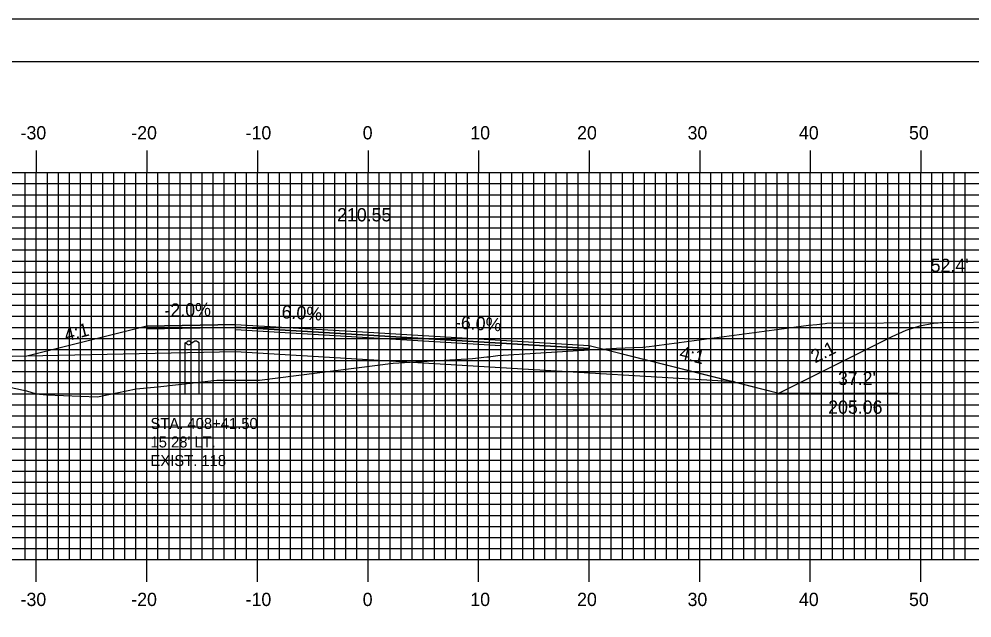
# Model space of a CAD drawing. Extents: x 852529 to 852872, y 364785 to 365005.
# Drawn here: x 852663.2 to 852749.3, y 364951 to 365005.1 of the extents above; entities that cross this region are included whole.
import ezdxf

# ---------------------------------------------------------------- set-up
doc = ezdxf.new("R2010")
doc.units = 0
for name, color, linetype in [('ANNOTATION', 7, 'Continuous'), ('BORDER', 7, 'Continuous'), ('D_Roadway_Centerline', 7, 'Continuous'), ('D_Roadway_Centerline_Text', 7, 'Continuous'), ('D_Roadway_Edge_Shoulder', 7, 'Continuous'), ('D_Roadway_Edge_TW', 7, 'Continuous'), ('D_Roadway_FinishedGrade', 7, 'Continuous'), ('D_Roadway_Pavement', 7, 'Continuous'), ('D_Roadway_SlopeLines', 7, 'Continuous'), ('D_Roadway_SubGrade', 7, 'Continuous'), ('D_Text_Monospaced', 7, 'Continuous'), ('D_Text_Standard', 7, 'Continuous'), ('H_V ANNOTATION', 7, 'Continuous'), ('MAJOR', 7, 'Continuous'), ('MINOR', 7, 'Continuous'), ('PDRAIN', 7, 'Continuous'), ('PLOT BOUNDARY', 7, 'Continuous'), ('S_Roadway_Centerline', 7, 'Continuous'), ('S_Utilities_Pole_Power', 7, 'Continuous')]:
    doc.layers.add(name, color=color, linetype=linetype)

msp = doc.modelspace()

# ---------------------------------------------------------------- linework, layer by layer
at = {"layer": 'ANNOTATION'}
msp.add_line((852663.861, 364974.628), (852637.933, 364974.11), dxfattribs=at)
at = {"layer": 'BORDER'}
msp.add_lwpolyline([(852545.131, 364791.233), (852865.131, 364791.233), (852865.131, 365001.233), (852545.131, 365001.233)], close=True, dxfattribs=at)
at = {"layer": 'D_Roadway_Centerline'}
msp.add_lwpolyline([(852674.731, 364977.346), (852682.731, 364977.506), (852694.731, 364976.786), (852706.731, 364976.066), (852714.731, 364975.586), (852727.889, 364972.296), (852731.889, 364971.296), (852742.137, 364976.42), (852743.387, 364976.968), (852744.637, 364977.363), (852745.887, 364977.603), (852747.137, 364977.69)], dxfattribs=at)
at = {"layer": 'D_Roadway_Edge_Shoulder'}
for points in [[(852682.731, 364977.506), (852674.731, 364977.346), (852674.731, 364977.096), (852682.731, 364977.256)], [(852706.731, 364976.066), (852714.731, 364975.586), (852714.731, 364975.336), (852706.731, 364975.816)]]:
    msp.add_lwpolyline(points, close=True, dxfattribs=at)
at = {"layer": 'D_Roadway_Edge_TW'}
msp.add_lwpolyline([(852682.731, 364977.256), (852682.731, 364977.506), (852694.731, 364976.786), (852706.731, 364976.066), (852706.731, 364975.816), (852694.731, 364976.536)], close=True, dxfattribs=at)
at = {"layer": 'D_Roadway_FinishedGrade'}
msp.add_line((852674.731, 364977.346), (852663.861, 364974.628), dxfattribs=at)
at = {"layer": 'D_Roadway_Pavement'}
msp.add_lwpolyline([(852682.731, 364977.006), (852682.731, 364977.256), (852694.731, 364976.536), (852706.731, 364975.816), (852706.731, 364975.566), (852694.731, 364976.286)], close=True, dxfattribs=at)
at = {"layer": 'D_Roadway_SlopeLines'}
for points in [[(852731.889, 364971.296), (852742.137, 364976.42), (852743.387, 364976.968), (852744.637, 364977.363), (852745.887, 364977.603), (852747.137, 364977.69)], [(852714.731, 364975.586), (852731.889, 364971.296)]]:
    msp.add_lwpolyline(points, dxfattribs=at)
at = {"layer": 'D_Roadway_SubGrade'}
msp.add_lwpolyline([(852674.731, 364977.346), (852674.731, 364977.096), (852682.731, 364977.256), (852694.731, 364976.536), (852706.731, 364975.816), (852714.731, 364975.336), (852714.731, 364975.586), (852727.889, 364972.296), (852706.731, 364973.566), (852694.731, 364974.286), (852682.731, 364975.006), (852663.861, 364974.628)], dxfattribs=at)
at = {"layer": 'MAJOR'}
for p, q in [((852664.731, 364993.237), (852664.731, 364991.233)), ((852674.731, 364993.237), (852674.731, 364991.233)), ((852684.731, 364993.237), (852684.731, 364991.233)), ((852694.731, 364993.237), (852694.731, 364991.233)), ((852704.731, 364993.237), (852704.731, 364991.233)), ((852714.731, 364993.237), (852714.731, 364991.233)), ((852724.731, 364993.237), (852724.731, 364991.233)), ((852734.731, 364993.237), (852734.731, 364991.233)), ((852744.731, 364993.237), (852744.731, 364991.233)), ((852554.731, 364991.233), (852834.731, 364991.233)), ((852554.731, 364991.233), (852834.731, 364991.233)), ((852664.731, 364956.233), (852664.731, 364991.233)), ((852674.731, 364956.233), (852674.731, 364991.233)), ((852684.731, 364956.233), (852684.731, 364991.233)), ((852694.731, 364956.233), (852694.731, 364991.233)), ((852704.731, 364956.233), (852704.731, 364991.233)), ((852714.731, 364956.233), (852714.731, 364991.233)), ((852724.731, 364956.233), (852724.731, 364991.233)), ((852734.731, 364956.233), (852734.731, 364991.233)), ((852744.731, 364956.233), (852744.731, 364991.233)), ((852554.731, 364986.233), (852834.731, 364986.233)), ((852554.731, 364981.233), (852834.731, 364981.233)), ((852554.731, 364976.233), (852834.731, 364976.233)), ((852554.731, 364971.233), (852834.731, 364971.233)), ((852554.731, 364966.233), (852834.731, 364966.233)), ((852554.731, 364961.233), (852834.731, 364961.233)), ((852554.731, 364956.233), (852834.731, 364956.233)), ((852554.731, 364956.233), (852834.731, 364956.233)), ((852664.731, 364954.229), (852664.731, 364956.233)), ((852674.731, 364954.229), (852674.731, 364956.233)), ((852684.731, 364954.229), (852684.731, 364956.233)), ((852694.731, 364954.229), (852694.731, 364956.233)), ((852704.731, 364954.229), (852704.731, 364956.233)), ((852714.731, 364954.229), (852714.731, 364956.233)), ((852724.731, 364954.229), (852724.731, 364956.233)), ((852734.731, 364954.229), (852734.731, 364956.233)), ((852744.731, 364954.229), (852744.731, 364956.233))]:
    msp.add_line(p, q, dxfattribs=at)
at = {"layer": 'MINOR'}
for p, q in [((852663.731, 364956.233), (852663.731, 364991.233)), ((852665.731, 364956.233), (852665.731, 364991.233)), ((852666.731, 364956.233), (852666.731, 364991.233)), ((852667.731, 364956.233), (852667.731, 364991.233)), ((852668.731, 364956.233), (852668.731, 364991.233)), ((852669.731, 364956.233), (852669.731, 364991.233)), ((852670.731, 364956.233), (852670.731, 364991.233)), ((852671.731, 364956.233), (852671.731, 364991.233)), ((852672.731, 364956.233), (852672.731, 364991.233)), ((852673.731, 364956.233), (852673.731, 364991.233)), ((852675.731, 364956.233), (852675.731, 364991.233)), ((852676.731, 364956.233), (852676.731, 364991.233)), ((852677.731, 364956.233), (852677.731, 364991.233)), ((852678.731, 364956.233), (852678.731, 364991.233)), ((852679.731, 364956.233), (852679.731, 364991.233)), ((852680.731, 364956.233), (852680.731, 364991.233)), ((852681.731, 364956.233), (852681.731, 364991.233)), ((852682.731, 364956.233), (852682.731, 364991.233)), ((852683.731, 364956.233), (852683.731, 364991.233)), ((852685.731, 364956.233), (852685.731, 364991.233)), ((852686.731, 364956.233), (852686.731, 364991.233)), ((852687.731, 364956.233), (852687.731, 364991.233)), ((852688.731, 364956.233), (852688.731, 364991.233)), ((852689.731, 364956.233), (852689.731, 364991.233)), ((852690.731, 364956.233), (852690.731, 364991.233)), ((852691.731, 364956.233), (852691.731, 364991.233)), ((852692.731, 364956.233), (852692.731, 364991.233)), ((852693.731, 364956.233), (852693.731, 364991.233)), ((852695.731, 364956.233), (852695.731, 364991.233)), ((852696.731, 364956.233), (852696.731, 364991.233)), ((852697.731, 364956.233), (852697.731, 364991.233)), ((852698.731, 364956.233), (852698.731, 364991.233)), ((852699.731, 364956.233), (852699.731, 364991.233)), ((852700.731, 364956.233), (852700.731, 364991.233)), ((852701.731, 364956.233), (852701.731, 364991.233)), ((852702.731, 364956.233), (852702.731, 364991.233)), ((852703.731, 364956.233), (852703.731, 364991.233)), ((852705.731, 364956.233), (852705.731, 364991.233)), ((852706.731, 364956.233), (852706.731, 364991.233)), ((852707.731, 364956.233), (852707.731, 364991.233)), ((852708.731, 364956.233), (852708.731, 364991.233)), ((852709.731, 364956.233), (852709.731, 364991.233)), ((852710.731, 364956.233), (852710.731, 364991.233)), ((852711.731, 364956.233), (852711.731, 364991.233)), ((852712.731, 364956.233), (852712.731, 364991.233)), ((852713.731, 364956.233), (852713.731, 364991.233)), ((852715.731, 364956.233), (852715.731, 364991.233)), ((852716.731, 364956.233), (852716.731, 364991.233)), ((852717.731, 364956.233), (852717.731, 364991.233)), ((852718.731, 364956.233), (852718.731, 364991.233)), ((852719.731, 364956.233), (852719.731, 364991.233)), ((852720.731, 364956.233), (852720.731, 364991.233)), ((852721.731, 364956.233), (852721.731, 364991.233)), ((852722.731, 364956.233), (852722.731, 364991.233)), ((852723.731, 364956.233), (852723.731, 364991.233)), ((852725.731, 364956.233), (852725.731, 364991.233)), ((852726.731, 364956.233), (852726.731, 364991.233)), ((852727.731, 364956.233), (852727.731, 364991.233)), ((852728.731, 364956.233), (852728.731, 364991.233)), ((852729.731, 364956.233), (852729.731, 364991.233)), ((852730.731, 364956.233), (852730.731, 364991.233)), ((852731.731, 364956.233), (852731.731, 364991.233)), ((852732.731, 364956.233), (852732.731, 364991.233)), ((852733.731, 364956.233), (852733.731, 364991.233)), ((852735.731, 364956.233), (852735.731, 364991.233)), ((852736.731, 364956.233), (852736.731, 364991.233)), ((852737.731, 364956.233), (852737.731, 364991.233)), ((852738.731, 364956.233), (852738.731, 364991.233)), ((852739.731, 364956.233), (852739.731, 364991.233)), ((852740.731, 364956.233), (852740.731, 364991.233)), ((852741.731, 364956.233), (852741.731, 364991.233)), ((852742.731, 364956.233), (852742.731, 364991.233)), ((852743.731, 364956.233), (852743.731, 364991.233)), ((852745.731, 364956.233), (852745.731, 364991.233)), ((852746.731, 364956.233), (852746.731, 364991.233)), ((852747.731, 364956.233), (852747.731, 364991.233)), ((852748.731, 364956.233), (852748.731, 364991.233)), ((852554.731, 364990.233), (852834.731, 364990.233)), ((852554.731, 364989.233), (852834.731, 364989.233)), ((852554.731, 364988.233), (852834.731, 364988.233)), ((852554.731, 364987.233), (852834.731, 364987.233)), ((852554.731, 364985.233), (852834.731, 364985.233)), ((852554.731, 364984.233), (852834.731, 364984.233)), ((852554.731, 364983.233), (852834.731, 364983.233)), ((852554.731, 364982.233), (852834.731, 364982.233)), ((852554.731, 364980.233), (852834.731, 364980.233)), ((852554.731, 364979.233), (852834.731, 364979.233)), ((852554.731, 364978.233), (852834.731, 364978.233)), ((852554.731, 364977.233), (852834.731, 364977.233)), ((852554.731, 364975.233), (852834.731, 364975.233)), ((852554.731, 364974.233), (852834.731, 364974.233)), ((852554.731, 364973.233), (852834.731, 364973.233)), ((852554.731, 364972.233), (852834.731, 364972.233)), ((852554.731, 364970.233), (852834.731, 364970.233)), ((852554.731, 364969.233), (852834.731, 364969.233)), ((852554.731, 364968.233), (852834.731, 364968.233)), ((852554.731, 364967.233), (852834.731, 364967.233)), ((852554.731, 364965.233), (852834.731, 364965.233)), ((852554.731, 364964.233), (852834.731, 364964.233)), ((852554.731, 364963.233), (852834.731, 364963.233)), ((852554.731, 364962.233), (852834.731, 364962.233)), ((852554.731, 364960.233), (852834.731, 364960.233)), ((852554.731, 364959.233), (852834.731, 364959.233)), ((852554.731, 364958.233), (852834.731, 364958.233)), ((852554.731, 364957.233), (852834.731, 364957.233))]:
    msp.add_line(p, q, dxfattribs=at)
at = {"layer": 'PDRAIN'}
msp.add_line((852731.889, 364971.296), (852742.66, 364971.296), dxfattribs=at)
at = {"layer": 'PLOT BOUNDARY'}
msp.add_lwpolyline([(852528.944, 364785.114), (852868.944, 364785.114), (852868.944, 365005.114), (852528.944, 365005.114)], close=True, dxfattribs=at)
at = {"layer": 'S_Roadway_Centerline'}
msp.add_lwpolyline([(852656.634, 364973.067), (852663.856, 364971.489), (852664.73, 364971.232), (852665.665, 364971.142), (852670.271, 364970.955), (852673.763, 364971.689), (852675.707, 364971.855), (852681.05, 364972.464), (852683.579, 364972.448), (852684.907, 364972.459), (852697.017, 364973.985), (852704.189, 364974.42), (852705.484, 364974.564), (852705.633, 364974.572), (852706.464, 364974.679), (852710.372, 364974.934), (852717.197, 364975.339), (852719.586, 364975.438), (852720.164, 364975.512), (852731.913, 364977.068), (852734.555, 364977.419), (852735.308, 364977.507), (852736.075, 364977.589), (852736.237, 364977.606), (852746.502, 364977.684), (852755.496, 364977.758)], dxfattribs=at)
at = {"layer": 'S_Utilities_Pole_Power'}
for p, q in [((852678.203, 364975.83), (852678.359, 364975.94)), ((852678.203, 364971.211), (852678.206, 364975.83)), ((852678.359, 364975.719), (852678.203, 364975.83)), ((852678.671, 364975.94), (852678.828, 364975.83)), ((852678.828, 364975.83), (852678.671, 364975.719)), ((852678.984, 364975.94), (852678.828, 364975.83)), ((852679.453, 364975.83), (852679.296, 364975.94)), ((852679.453, 364971.211), (852679.456, 364975.83))]:
    msp.add_line(p, q, dxfattribs=at)
for centre, start, end in [((852678.515, 364975.719), 90, 125.26439), ((852678.515, 364975.719), 54.73561, 90), ((852679.14, 364975.719), 90, 125.26439), ((852679.14, 364975.719), 54.73561, 90), ((852678.515, 364975.94), 234.73561, 270), ((852678.515, 364975.94), 270, 305.26439)]:
    msp.add_arc(centre, 0.271, start, end, dxfattribs=at)

# ---------------------------------------------------------------- texts
at = {"layer": 'ANNOTATION'}
for s, rotation, p in [('-2.0%', 1.14576, (852676.337, 364978.178)), ('6.0%', 356.56637, (852686.885, 364978.06)), ('4:1', 14.03624, (852667.432, 364975.966)), ('-6.0%', 356.56637, (852702.565, 364977.119)), ('2:1', 26.56505, (852735.158, 364973.967)), ('4:1', 345.96376, (852722.815, 364974.426))]:
    msp.add_text(s, height=1.2, rotation=rotation, dxfattribs=at).set_placement(p)
for s, p in [("37.2'", (852737.231, 364972.022)), ('205.06', (852736.347, 364969.422))]:
    msp.add_text(s, height=1.2, dxfattribs=at).set_placement(p)
at = {"layer": 'D_Roadway_Centerline'}
for s, p in [('C', (852694.725, 364976.786)), ('L', (852694.731, 364976.778))]:
    msp.add_text(s, height=0.0146, dxfattribs=at).set_placement(p)
at = {"layer": 'D_Roadway_Centerline_Text'}
msp.add_text('210.55', height=1.2, dxfattribs=at).set_placement((852691.932, 364986.816))
at = {"layer": 'D_Text_Monospaced'}
for s, height, p in [('STA. 408+41.50', 0.99996, (852675.054, 364968.04)), ("15.28' LT.", 1, (852675.054, 364966.372)), ('EXIST. 118', 1, (852675.054, 364964.692))]:
    msp.add_text(s, height=height, dxfattribs=at).set_placement(p)
at = {"layer": 'D_Text_Standard'}
msp.add_text("52.4'", height=1.2, dxfattribs=at).set_placement((852745.62, 364982.242))
at = {"layer": 'H_V ANNOTATION'}
for s, p in [('-30', (852663.307, 364994.233)), ('-20', (852673.318, 364994.233)), ('-10', (852683.66, 364994.233)), ('0', (852694.249, 364994.233)), ('10', (852703.981, 364994.233)), ('20', (852713.639, 364994.233)), ('30', (852723.628, 364994.233)), ('40', (852733.703, 364994.233)), ('50', (852743.66, 364994.233)), ('-30', (852663.307, 364952.033)), ('-20', (852673.318, 364952.033)), ('-10', (852683.66, 364952.033)), ('0', (852694.249, 364952.033)), ('10', (852703.981, 364952.033)), ('20', (852713.639, 364952.033)), ('30', (852723.628, 364952.033)), ('40', (852733.703, 364952.033)), ('50', (852743.66, 364952.033))]:
    msp.add_text(s, height=1.2, dxfattribs=at).set_placement(p)

doc.saveas('drawing.dxf')
